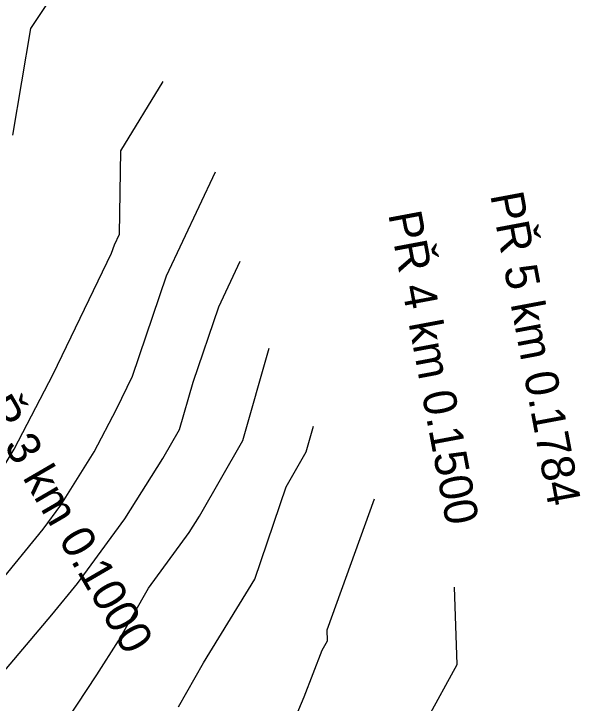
# Model space of a CAD drawing. Extents: x -549394 to -546608, y -1037055 to -1033629.
# Drawn here: x -547431.1 to -547276.3, y -1035096.6 to -1034908.3 of the extents above; entities that cross this region are included whole.
import ezdxf

# ---------------------------------------------------------------- set-up
doc = ezdxf.new("R2010")
doc.units = 0
for name, color, linetype in [('hlavni_vrst', 7, 'Continuous'), ('norm_vrst', 7, 'Continuous'), ('x_popis_pricne_rezy_C14', 7, 'Continuous')]:
    doc.layers.add(name, color=color, linetype=linetype)

msp = doc.modelspace()

# ---------------------------------------------------------------- linework, layer by layer
at = {"layer": 'hlavni_vrst'}
for p, q in [((-547389.33, -1034979.93), (-547375.98, -1034951.49)), ((-547398.7, -1035007.27), (-547389.33, -1034979.93)), ((-547403.08, -1035016.36), (-547398.7, -1035007.27)), ((-547409.12, -1035027.98), (-547403.08, -1035016.36)), ((-547418.29, -1035042.55), (-547409.12, -1035027.98)), ((-547423.11, -1035049.09), (-547418.29, -1035042.55)), ((-547439.63, -1035069.29), (-547423.11, -1035049.09)), ((-547309.93, -1035086.01), (-547310.62, -1035064.9)), ((-547321.67, -1035107.49), (-547309.93, -1035086.01))]:
    msp.add_line(p, q, dxfattribs=at)
at = {"layer": 'norm_vrst'}
for p, q in [((-547426.48, -1034912.33), (-547413.93, -1034893.43)), ((-547431.35, -1034941.44), (-547426.48, -1034912.33)), ((-547401.87, -1034945.73), (-547390.31, -1034926.86)), ((-547402.24, -1034968.56), (-547401.87, -1034945.73)), ((-547403.61, -1034971.46), (-547402.24, -1034968.56)), ((-547404.38, -1034973.72), (-547403.61, -1034971.46)), ((-547420.31, -1035006.73), (-547404.38, -1034973.72)), ((-547375.06, -1034988.39), (-547369.21, -1034975.93)), ((-547382.1, -1035008.94), (-547375.06, -1034988.39)), ((-547368.51, -1035024.92), (-547361.28, -1034999.68)), ((-547430.97, -1035027.25), (-547420.31, -1035006.73)), ((-547385.81, -1035021.9), (-547382.1, -1035008.94)), ((-547351.21, -1035027.95), (-547349.22, -1035021)), ((-547390.34, -1035029.8), (-547385.81, -1035021.9)), ((-547380.35, -1035045.58), (-547368.51, -1035024.92)), ((-547436.64, -1035036.48), (-547430.97, -1035027.25)), ((-547356.68, -1035037.5), (-547351.21, -1035027.95)), ((-547400.72, -1035046.29), (-547390.34, -1035029.8)), ((-547365.24, -1035062.74), (-547356.68, -1035037.5)), ((-547345.49, -1035076.61), (-547332.56, -1035040.77)), ((-547383.15, -1035050.04), (-547380.35, -1035045.58)), ((-547413.72, -1035063.93), (-547400.72, -1035046.29)), ((-547394.33, -1035065.22), (-547383.15, -1035050.04)), ((-547420.74, -1035072.52), (-547413.72, -1035063.93)), ((-547379.26, -1035085.64), (-547365.24, -1035062.74)), ((-547402.49, -1035079.59), (-547394.33, -1035065.22)), ((-547440.38, -1035095.64), (-547420.74, -1035072.52)), ((-547345.39, -1035079.55), (-547345.49, -1035076.61)), ((-547346.81, -1035082.13), (-547345.39, -1035079.55)), ((-547408.42, -1035088.9), (-547402.49, -1035079.59)), ((-547351.76, -1035094.86), (-547346.81, -1035082.13)), ((-547386.05, -1035097.61), (-547379.26, -1035085.64)), ((-547424.58, -1035113.3), (-547408.42, -1035088.9)), ((-547363.97, -1035124.4), (-547351.76, -1035094.86))]:
    msp.add_line(p, q, dxfattribs=at)

# ---------------------------------------------------------------- texts
at = {"layer": 'x_popis_pricne_rezy_C14'}
for s, rotation, p in [('PŘ 5 km 0.1784', 280.6108, (-547300.91, -1034957.79)), ('PŘ 4 km 0.1500', 280.6108, (-547328.79, -1034963.02)), ('PŘ 3 km 0.1000', 300.1864, (-547444.08, -1035008.78))]:
    msp.add_text(s, height=9.0627, rotation=rotation, dxfattribs=at).set_placement(p)

doc.saveas('drawing.dxf')
